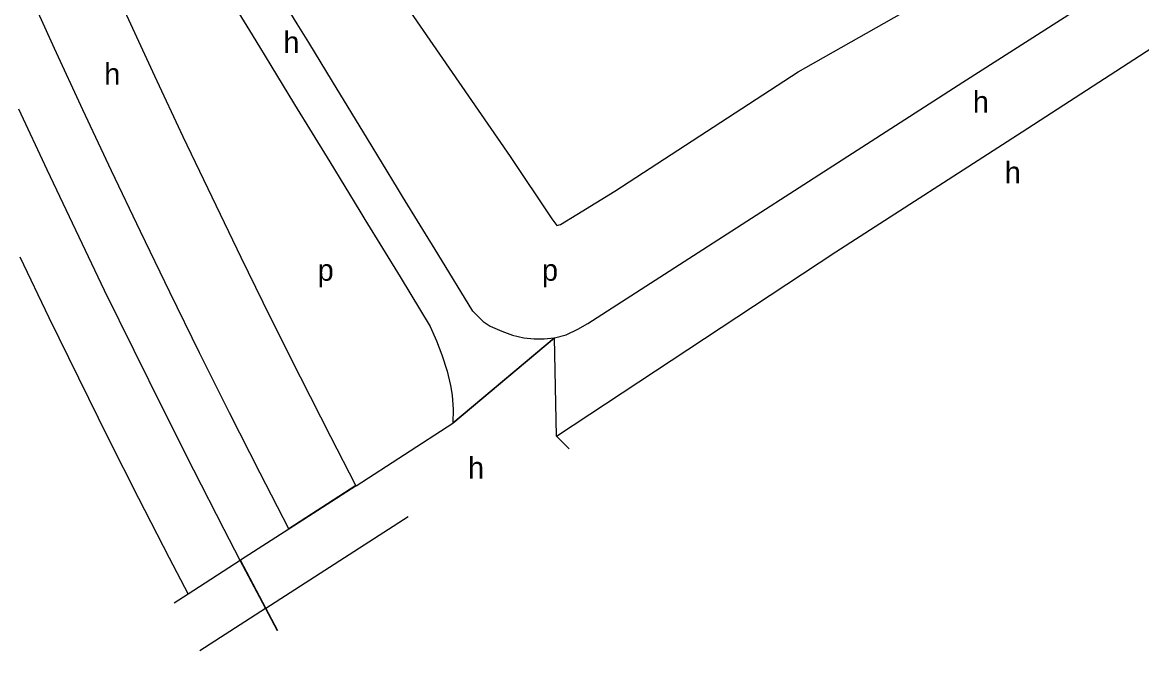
# Model space of a CAD drawing. Extents: x 156097 to 158136, y 385644 to 388348.
# Drawn here: x 156481.1 to 156688.7, y 385644.5 to 385761.1 of the extents above; entities that cross this region are included whole.
import ezdxf

# ---------------------------------------------------------------- set-up
doc = ezdxf.new("R2010")
doc.units = 0
for name, color, linetype in [('BLT_Basislijn', 7, 'Continuous'), ('BLT_Centroide', 7, 'Continuous'), ('BLT_Vlakafsluiter', 7, 'Continuous')]:
    doc.layers.add(name, color=color, linetype=linetype)

msp = doc.modelspace()

# ---------------------------------------------------------------- linework, layer by layer
at = {"layer": 'BLT_Basislijn'}
for p, q in [((156542.97, 385675.1), (156560.95, 385686.71)), ((156542.97, 385675.1), (156530.52, 385667.06)), ((156530.52, 385667.06), (156521.54, 385661.26)), ((156521.5, 385661.23), (156511.8, 385654.96)), ((156521.54, 385661.26), (156521.5, 385661.23)), ((156511.8, 385654.96), (156509.22, 385653.3))]:
    msp.add_line(p, q, dxfattribs=at)
for points in [[(156530.5, 385667.1), (156525.16, 385677.46), (156519.51, 385688.61), (156513.92, 385699.8), (156508.4, 385711.02), (156502.96, 385722.28), (156497.58, 385733.57), (156492.28, 385744.9), (156487.05, 385756.26), (156481.89, 385767.65), (156476.81, 385779.07), (156471.79, 385790.53), (156466.85, 385802.02), (156461.98, 385813.53), (156457.19, 385825.08), (156452.47, 385836.66), (156447.82, 385848.27), (156443.24, 385859.91), (156438.74, 385871.58), (156434.31, 385883.27), (156429.96, 385895), (156425.68, 385906.75), (156421.48, 385918.52)], [(156542.95, 385675.15), (156538.3, 385684.18), (156532.68, 385695.25), (156527.13, 385706.35), (156521.66, 385717.49), (156516.26, 385728.66), (156510.92, 385739.87), (156505.66, 385751.11), (156500.47, 385762.38), (156495.35, 385773.69), (156490.3, 385785.03), (156485.32, 385796.4), (156480.42, 385807.8), (156475.59, 385819.23), (156470.83, 385830.7), (156466.14, 385842.19), (156461.53, 385853.71), (156456.99, 385865.26), (156452.52, 385876.84), (156448.13, 385888.45), (156443.81, 385900.09), (156439.56, 385911.75), (156438.83, 385913.77)], [(156495.21, 385842.48), (156501.15, 385835.15), (156506.61, 385828.62), (156517.16, 385814.39), (156536.92, 385786.48), (156571.53, 385736.24), (156579.3, 385724.63), (156580.22, 385723.41), (156580.87, 385723.57), (156583.92, 385725.46), (156590.96, 385729.81), (156624.96, 385751.91), (156655.44, 385769.28), (156679.53, 385783.05), (156691.99, 385789.62)], [(156564.63, 385707.48), (156558.12, 385718.15), (156551.61, 385728.82), (156550.67, 385730.36), (156545.1, 385739.49), (156538.58, 385750.16), (156534.18, 385757.37), (156532.07, 385760.82), (156530.19, 385763.91), (156525.57, 385771.49), (156519.09, 385782.16), (156512.66, 385792.84), (156506.28, 385803.54), (156503.11, 385808.9), (156499.97, 385814.27), (156496.84, 385819.65), (156493.75, 385825.03), (156490.62, 385830.41), (156487.53, 385835.79), (156484.47, 385841.19)], [(156579.78, 385702.58), (156581.93, 385703.11), (156584.13, 385704.14), (156585.94, 385705.23), (156655.52, 385750), (156697.54, 385776.91), (156725.81, 385791.53)], [(156580.15, 385684.3), (156631.95, 385718.54), (156666.5, 385740.78), (156691.63, 385757.06), (156716.85, 385773.3)], [(156518.56, 385767.23), (156523.19, 385759.64), (156525.07, 385756.55), (156527.18, 385753.09), (156531.58, 385745.88), (156538.1, 385735.21), (156543.67, 385726.09), (156544.61, 385724.54), (156551.12, 385713.87), (156556.74, 385704.67), (156557.9, 385701.99), (156558.88, 385699.43), (156559.85, 385696.39), (156560.48, 385693.73), (156560.77, 385691.94), (156560.99, 385689.24), (156560.95, 385686.78)], [(156521.5, 385661.23), (156518.53, 385666.95), (156512.88, 385678), (156507.3, 385689.09), (156501.79, 385700.21), (156496.34, 385711.36), (156490.97, 385722.55), (156485.67, 385733.77), (156480.43, 385745.02)], [(156480.59, 385717.6), (156485.99, 385706.35), (156491.47, 385695.13), (156497.01, 385683.95), (156502.62, 385672.8), (156508.31, 385661.69), (156511.8, 385654.96)], [(156564.63, 385707.48), (156566.52, 385705.58), (156567.85, 385704.74), (156569.99, 385703.77), (156572, 385703.07), (156574.08, 385702.59), (156575.98, 385702.4), (156577.88, 385702.4), (156579.7, 385702.57)], [(156579.7, 385702.57), (156579.78, 385702.58)], [(156560.95, 385686.78), (156560.95, 385686.71)], [(156542.97, 385675.1), (156542.95, 385675.15)], [(156526.24, 385652.38), (156552.63, 385669.4)], [(156530.52, 385667.06), (156530.5, 385667.1)], [(156514, 385644.49), (156526.19, 385652.35)], [(156526.19, 385652.35), (156526.24, 385652.38)]]:
    msp.add_lwpolyline(points, dxfattribs=at)
at = {"layer": 'BLT_Vlakafsluiter'}
for p, q in [((156560.95, 385686.71), (156579.78, 385702.58)), ((156560.95, 385686.78), (156579.7, 385702.57)), ((156580.15, 385684.3), (156579.78, 385702.58)), ((156582.5, 385681.96), (156580.15, 385684.3)), ((156542.95, 385675.15), (156530.5, 385667.1)), ((156526.19, 385652.35), (156521.5, 385661.23)), ((156526.24, 385652.38), (156521.54, 385661.26)), ((156528.41, 385648.16), (156526.19, 385652.35)), ((156528.46, 385648.18), (156526.24, 385652.38))]:
    msp.add_line(p, q, dxfattribs=at)

# ---------------------------------------------------------------- texts
at = {"layer": 'BLT_Centroide'}
for s, p in [('h', (156529.49, 385755.42)), ('h', (156496.26, 385749.53)), ('h', (156657.37, 385744.36)), ('h', (156663.3, 385731.26)), ('p', (156535.85, 385713.15)), ('p', (156577.46, 385713.15)), ('h', (156563.74, 385676.44))]:
    msp.add_text(s, height=4, dxfattribs=at).set_placement(p)

doc.saveas('drawing.dxf')
